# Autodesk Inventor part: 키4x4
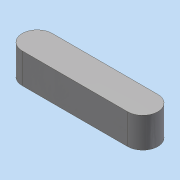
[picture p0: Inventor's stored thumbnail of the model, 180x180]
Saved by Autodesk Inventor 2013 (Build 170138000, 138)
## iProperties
Company: 한국ATC센터
Created: 2009-02
Part Number: 키4x4
Document SubType Name: Modeling
Designer: KYOUNG IL JANG
Density: 7.86 g/cm^3
Mass: 2.15573 g
Surface Area: 2.99398 cm^2
Volume: 0.274265 cm^3
Vendor: CBT Solutions
Material: 강철, 연강
Author: KYOUNG IL JANG
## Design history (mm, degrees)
sketch "스케치1"
  geometry: L1 (0, 2)-(14, 2); L2 (0, -2)-(14, -2); A1 r 2 centre (0, 0) between (0, 2) and (0, -2); A2 r 2 centre (14, 0) between (14, -2) and (14, 2); 1 further point
  constraints: 4 end point, 4 point on circle, 3 tangent, 2 centre point, 1 coincident, 1 equal radius, 1 horizontal alignment, 1 parallel
  dimensions: "d0" = 4 distance between parallel lines of L2 L1; "d1" = 18 dimension on A2 A1
extrude "돌출1" new body sketch "스케치1" distance "d2" = 4; taper "d3" = 0 deg
node "솔리드1"
